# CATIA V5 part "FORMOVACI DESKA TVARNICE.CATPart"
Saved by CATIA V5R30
Part number: FORMOVACI DESKA TVARNICE
Bounding box of the stored display mesh (mm): x 0 to 66, y -248 to 248, z -173 to 173
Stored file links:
  C:\Users\ondra\Desktop\PŘÍLOHA P III\CATIA\FORMOVACI DESKA TVARNICE.CATPart
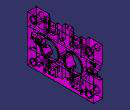
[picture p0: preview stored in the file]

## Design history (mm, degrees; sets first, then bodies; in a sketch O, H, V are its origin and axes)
Set1
  DatumSurface1 to DatumSurface42 "K20/346x"
  Plane1: type Tangent, Support DatumSurface41, RefPoint vertex [face of DatumSurface42]
  Plane2: type Tangent, Support DatumSurface39, RefPoint vertex [face of DatumSurface38]
  Plane3: type Offset, RefPlane yz-plane, Offset 66
  Join1: Elements (DatumSurface1; DatumSurface2; DatumSurface3; DatumSurface4; DatumSurface5; DatumSurface6; DatumSurface7; DatumSurface8; DatumSurface9; DatumSurface10; DatumSurface11; DatumSurface12; DatumSurface13; DatumSurface14; DatumSurface15; DatumSurface16; DatumSurface17; DatumSurface18; DatumSurface19; DatumSurface20; DatumSurface21; DatumSurface22; DatumSurface23; DatumSurface24; DatumSurface25; DatumSurface26; DatumSurface27; DatumSurface28; DatumSurface29; DatumSurface30; DatumSurface31; DatumSurface32; DatumSurface33; DatumSurface34; DatumSurface35; DatumSurface36; DatumSurface37; DatumSurface38; DatumSurface39; DatumSurface40; DatumSurface41; DatumSurface42)
Body1 (main body)
  CloseSurface1: CloseElement Join1
  DatumCurve1 to DatumCurve4
  Sketch1 on yz-plane, origin (0, 0, 0), H (0, 1, 0), V (0, 0, 1)
    projected arc E1 centre (0, 0) radius 9 from (0, 9) to (0, -9) ccw from edge of DatumCurve3
    projected arc E2 centre (0, 0) radius 9 from (0, -9) to (0, 9) ccw from edge of DatumCurve4
  Pocket1: profile Sketch1, direction (-1, 0, 0), through (limit type 6)
  DatumSurface43
  DatumSurface44
  Sketch2 on yz-plane, origin (0, 0, 0), H (0, 1, 0), V (0, 0, 1)
    reference projected circle E1 centre (-88.524, 0) radius 75 from face of DatumSurface43
    reference projected circle E2 centre (88.524, 0) radius 75 from face of DatumSurface44
    point P1 (-88.524, 0)
    point P2 (88.524, 0)
    concentricity: P1 E1, P2 E2
  Sketch3 on {plane type Tangent, Support face of DatumSurface42, RefPoint Sketch2.P1}, origin (0, -88.524, 0), H (0, 1, 0), V (0, 0, 1)
    point P1 (0, 0)
    reference projected point E1 (0, 0) from Sketch2.P1
    coincidence: E1 P1
  Hole1: placed by Sketch3, at (66, -88.524, 0) direction (-1, 0, 0), diameter 130, through (limit type 6), counterbore diameter 140, counterbore depth 10
  UserPattern1: of Hole1, copies 2, at the points of Sketch2
  Plane4: stored without definition
  Fillet1: radius 1, on edge [face of Hole1 | face of Hole1] (x2); edge [face of UserPattern1 | face of UserPattern1] (x2)
  Sketch4 on zx-plane, origin (0, 0, 0), H (-1, 0, 0), V (0, 0, 1)
    arc A1 centre (0, 0) radius 2.5 from (0, 2.5) to (0, -2.5) ccw
    line L1 (0, -2.5) -> (0, 2.5)
    point P1 (0, -2.5)
    radius A1 = 2.5
    coincidence: P1 V
    vertical: L1 V
  Pocket2: profile Sketch4, direction (0, 1, 0), through (limit type 6), opposite side through (limit type 6)
  Sketch5, origin (66, 0, 0), H (0, 1, 0), V (0, 0, -1), geometry linked from another document
  Pocket3: profile Sketch5, direction (-1, 0, 0), length 7
  Plane5: stored without definition
  Plane6: stored without definition
  Mirror1: of Pocket3, about Plane5
  DatumCurve5
  DatumCurve6
  Sketch6 on Plane6, origin (0, -248, 0), H (-1, 0, 0), V (0, 0, 1)
    point P1 (-47, 71)
    point P2 (-47, -71)
    point P3 (13, 71)
    construction line L1 (-47, -71) -> (-47, 71)
    reference projected line E1 (-66, 173) -> (-66, -173) from edge of DatumCurve6
    reference projected line E2 (-66, 173) -> (0, 173) from edge [face of CloseSurface1 | face of CloseSurface1]
    reference projected line E3 (0, -173) -> (-66, -173) from edge [face of CloseSurface1 | face of CloseSurface1]
    distance P1 E1 = 19
    distance P1 E2 = 102
    distance P2 E3 = 102
    vertical: L1 V
  Sketch7 on {plane type Tangent, Support face of CloseSurface1, RefPoint Sketch6.P1}, origin (47, -248, 71), H (1, 0, 0), V (0, 0, -1)
    point P1 (0, 0)
    reference projected point E1 (0, 0) from Sketch6.P1
    coincidence: E1 P1
  Hole2: placed by Sketch7, at (47, -248, 71) direction (0, 1, 0), diameter 8.376, through (limit type 6), counterbore diameter 14, counterbore depth 3, threaded "M10", thread diameter 10, thread depth 9, pitch 1.5
  Plane7: stored without definition
  UserPattern2: of Hole2, copies 2, at the points of Sketch6
  Sketch8 on Plane7, origin (0, 0, -173), H (1, 0, 0), V (0, -1, 0)
    point P1 (47, 137.5)
    point P2 (47, -137.5)
    construction line L1 (47, -137.5) -> (47, 137.5)
    reference projected line E1 (66, -248) -> (66, 248) from edge [face of CloseSurface1 | face of CloseSurface1]
    distance E1 L1 = 19
    length L1 = 275
    symmetry: P1 P2 H
    vertical: L1 V
  Sketch9 on {plane type Tangent, Support face of CloseSurface1, RefPoint Sketch8.P1}, origin (48, -137.5, -173), H (1, 0, 0), V (0, 1, 0)
    point P1 (-1, 0)
    reference projected point E1 (-1, 0) from Sketch8.P1
    coincidence: E1 P1
  Hole3: placed by Sketch9, at (47, -137.5, -173) direction (0, 0, 1), diameter 8.376, depth 110, V-bottom angle 120, counterbore diameter 16, counterbore depth 17, threaded "M10", thread diameter 10, thread depth 8, pitch 1.5
  UserPattern3: of Hole3, copies 2, at the points of Sketch8
  Plane8: stored without definition
  Mirror2: of UserPattern3, about Plane8
  Plane9: stored without definition
  Plane10: type Offset, RefPlane Plane9, Offset 248, reversed
  Plane11: type Offset, RefPlane Plane10, Offset 496
  Plane12: type Offset, RefPlane xy-plane, Offset 173
  Plane13: type Offset, RefPlane xy-plane, Offset 173, reversed
  DatumCurve7 to DatumCurve9
  Sketch10 on Plane11, origin (0, 248, 0), H (-1, 0, 0), V (0, 0, 1)
    reference projected line E3 (-8.3275, -47.5) -> (3.6725, -47.5) from edge of DatumCurve8
    line L1 (0, 47.5) -> (-19.3275, 47.5)
    line L2 (-19.3275, 47.5) -> (-19.3275, -47.5)
    line L3 (-19.3275, -47.5) -> (0, -47.5)
    line L4 (0, -47.5) -> (0, 47.5)
    point P8 (-19.3275, -47.5)
    reference projected line E4 (-19.3275, -47) -> (-19.3275, -32) from edge of DatumCurve9
    horizontal: L1 H, L3 H
    vertical: L2 V, L4 V
    coincidence: P8 E3, E4 L2
  Pocket4: profile Sketch10, direction (0, -1, 0), length 71
  DatumSurface45
  Sketch11 on Plane11, origin (0, 248, 0), H (-1, 0, 0), V (0, 0, 1)
  Pocket5: profile Sketch11, direction (0, -1, 0), length 65
  DatumCurve10 to DatumCurve16
  Sketch12 on Plane11, origin (0, 248, 0), H (-1, 0, 0), V (0, 0, 1)
    projected line E1 (-36.4678, -19) -> (-36.4678, 19) from edge [face of Pocket5 | face of CloseSurface1]
    projected line E2 (-46.4678, 19) -> (-36.4678, 19) from edge of DatumCurve10
    projected line E3 (-46.4678, 19) -> (-46.4678, 18.8) from edge of DatumCurve11
    projected line E4 (-46.4678, 12.8) -> (-46.4678, 18.8) from edge of DatumCurve12
    projected line E5 (-46.4678, 12.8) -> (-46.4678, -12.8) from edge of DatumCurve13
    projected line E6 (-46.4678, -18.8) -> (-46.4678, -12.8) from edge of DatumCurve14
    projected line E7 (-46.4678, -18.8) -> (-46.4678, -19) from edge of DatumCurve15
    projected line E8 (-46.4678, -19) -> (-36.4678, -19) from edge of DatumCurve16
  Pocket6: profile Sketch12, direction (0, -1, 0), length 65, opposite side length -40
  Fillet2: radius 6, on edge [start face of Pocket6 | face of Pocket6] (x2); edge [face of Pocket6 | face of Pocket6] (x2)
  DatumCurve17 to DatumCurve19
  Sketch13 on yz-plane, origin (0, 0, 0), H (0, 1, 0), V (0, 0, 1)
    reference projected line E3 (220.3458, -34.5) -> (170.3458, -34.5) from edge of DatumCurve19
    reference projected line E4 (177, 47.5) -> (177, -47.5) from edge [end face of Pocket4 | face of CloseSurface1]
    line L1 (177, -34.5) -> (170.3458, -34.5)
    point P9 (177, -34.5)
    line L2 (170.3458, -34.5) -> (170.3458, 34.5)
    line L3 (170.3458, 34.5) -> (177, 34.5)
    point P10 (177, 34.5)
    line L4 (177, 34.5) -> (177, -34.5)
    coincidence: P9 E4, P9 E3, P10 E4
    horizontal: L1 H, L3 H
    vertical: L2 V, L4 V
  Pocket7: profile Sketch13, direction (1, 0, 0), length 10
  Plane14: type Offset, RefPlane xy-plane, Offset 31.5, reversed
  DatumCurve20 to DatumCurve23
  Sketch14 on Plane14, origin (0, 0, -31.5), H (1, 0, 0), V (0, 1, 0)
    projected arc E2 centre (22.3275, 212.394) radius 2 from (24.3275, 212.394) to (23.0115, 214.2733) ccw from edge of DatumCurve21
    line L1 (10.1275, 218.9627) -> (0, 218.9627)
    point P7 (0, 218.9627)
    reference projected line E4 (4.3275, 147.5358) -> (24.3275, 147.5358) from edge of DatumCurve23
    line L2 (0, 218.9627) -> (0, 147.5358)
    point P10 (0, 147.5358)
    line L3 (0, 147.5358) -> (24.3275, 147.5358)
    line L4 (24.3275, 147.5358) -> (24.3275, 212.394)
    line L5 (23.0115, 214.2733) -> (10.1275, 218.9627)
    coincidence: P7 V, P10 E4
    horizontal: L1 H, L3 H
    vertical: L2 V
    tangency: L4 E2, L5 E2
  Pocket8: profile Sketch14, direction (0, 0, 1), length 63
  Sketch15 on face of Pocket8 from Sketch14.L3, origin (0, 147.5358, 0), H (-1, 0, 0), V (0, 0, 1)
    line L1 (-24.3275, -31.5) -> (0, -31.5)
    line L2 (0, -31.5) -> (0, 31.5)
    line L3 (0, 31.5) -> (-24.3275, 31.5)
    line L4 (-24.3275, 31.5) -> (-24.3275, -31.5)
    horizontal: L1 H, L3 H
    vertical: L2 V, L4 V
  Pocket9: profile Sketch15, direction (0, -1, 0), length 5
  Mirror3: of Pocket4, Pocket5, Pocket6, Fillet2, Pocket7, Pocket8, Pocket9, about zx-plane
  DatumCurve24 to DatumCurve27
  Sketch16 on Plane12, origin (0, 0, 173), H (1, 0, 0), V (0, 1, 0)
    point P11 (0, 148.524)
    line L1 (0, 148.524) -> (26.5427, 148.524)
    line L2 (26.5427, 148.524) -> (26.5427, 28.524)
    line L3 (26.5427, 28.524) -> (0, 28.524)
    line L4 (0, 28.524) -> (0, 148.524)
    point P13 (26.5427, 28.524)
    point P16 (0, -148.524)
    line L5 (0, -148.524) -> (26.5427, -148.524)
    point P17 (26.5427, -28.524)
    line L6 (26.5427, -148.524) -> (26.5427, -28.524)
    line L7 (26.5427, -28.524) -> (0, -28.524)
    line L8 (0, -28.524) -> (0, -148.524)
    coincidence: P11 V
    horizontal: L1 H, L3 H
    vertical: L2 V, L4 V
    symmetry: P11 P16 H, P13 P17 H
  Pocket10: profile Sketch16, direction (0, 0, -1), length 101.008
  DatumCurve28 to DatumCurve30
  Sketch17 on face of Pocket10 from Sketch16.L6, origin (26.5427, 0, 0), H (0, -1, 0), V (0, 0, 1)
    reference projected line E1 (62.024, 171.9919) -> (62.024, 147.7272) from edge of DatumCurve28
    reference projected line E2 (148.524, 173) -> (28.524, 173) from edge [face of CloseSurface1 | face of Pocket10 from Sketch16.L6]
    reference projected line E3 (108.824, 100.9919) -> (68.224, 100.9919) from edge of DatumCurve29
    reference projected line E4 (115.024, 147.7272) -> (115.024, 171.9919) from edge of DatumCurve30
    point P9 (62.024, 173)
    line L1 (62.024, 173) -> (115.024, 173)
    line L2 (115.024, 173) -> (115.024, 100.9919)
    line L3 (115.024, 100.9919) -> (62.024, 100.9919)
    line L4 (62.024, 100.9919) -> (62.024, 173)
    point P10 (115.024, 173)
    point P11 (115.024, 100.9919)
    point P12 (62.024, 100.9919)
    point P13 (-115.024, 173)
    point P14 (-62.024, 173)
    line L5 (-62.024, 173) -> (-115.024, 173)
    point P15 (-115.024, 100.9919)
    line L6 (-115.024, 173) -> (-115.024, 100.9919)
    point P16 (-62.024, 100.9919)
    line L7 (-115.024, 100.9919) -> (-62.024, 100.9919)
    line L8 (-62.024, 100.9919) -> (-62.024, 173)
    coincidence: P9 E2, P9 E1, P11 E4, P11 E3
    horizontal: L1 H, L3 H
    vertical: L2 V, L4 V
    symmetry: P10 P13 V, P9 P14 V, L1 L5 V, P11 P15 V, L2 L6 V, P12 P16 V, L3 L7 V, L4 L8 V
  Pocket11: profile Sketch17, direction (1, 0, 0), length 15
  DatumCurve31 to DatumCurve34
  Sketch18 on face of Pocket10 from Sketch16.L6, origin (26.5427, 0, 0), H (0, -1, 0), V (0, 0, 1)
    reference projected line E1 (108.824, 100.9919) -> (68.224, 100.9919) from edge of DatumCurve31
    reference projected line E2 (115.024, 119.7919) -> (115.024, 107.1919) from edge of DatumCurve32
    reference projected line E3 (68.224, 125.9919) -> (108.824, 125.9919) from edge of DatumCurve33
    reference projected line E4 (62.024, 107.1919) -> (62.024, 119.7919) from edge of DatumCurve34
    point P9 (62.024, 125.9919)
    line L1 (62.024, 125.9919) -> (115.024, 125.9919)
    line L2 (115.024, 125.9919) -> (115.024, 100.9919)
    line L3 (115.024, 100.9919) -> (62.024, 100.9919)
    line L4 (62.024, 100.9919) -> (62.024, 125.9919)
    point P10 (115.024, 125.9919)
    point P11 (115.024, 100.9919)
    point P12 (62.024, 100.9919)
    point P13 (-115.024, 100.9919)
    point P14 (-115.024, 125.9919)
    line L5 (-115.024, 125.9919) -> (-115.024, 100.9919)
    point P15 (-62.024, 125.9919)
    line L6 (-62.024, 125.9919) -> (-115.024, 125.9919)
    point P16 (-62.024, 100.9919)
    line L7 (-62.024, 100.9919) -> (-62.024, 125.9919)
    line L8 (-115.024, 100.9919) -> (-62.024, 100.9919)
    coincidence: P9 E4, P9 E3, P11 E2, P11 E1
    horizontal: L1 H, L3 H
    vertical: L2 V, L4 V
    symmetry: P11 P13 V, P10 P14 V, L2 L5 V, P9 P15 V, L1 L6 V, P12 P16 V, L4 L7 V, L3 L8 V
  Pocket12: profile Sketch18, direction (1, 0, 0), length 27
  Fillet3: radius 6, on edge [face of Pocket12 | face of Pocket12] (x4); edge [face of Pocket12 from Sketch18.L1 | face of Pocket12]; edge [face of Pocket12 | face of Pocket12 from Sketch18.L1]; edge [face of Pocket12 from Sketch18.L6 | face of Pocket12]; edge [face of Pocket12 | face of Pocket12 from Sketch18.L6]
  DatumCurve35 to DatumCurve39
  Sketch19 on yz-plane, origin (0, 0, 0), H (0, 1, 0), V (0, 0, 1)
    reference projected line E1 (-54.0014, 37.4203) -> (-54.0014, 57.0375) from edge of DatumCurve35
    point P2 (-54.0014, 57.0375)
    point P3 (-48.524, 57.0375)
    reference projected line E3 (-123.0467, 37.4203) -> (-123.0467, 57.0375) from edge of DatumCurve37
    point P6 (-123.0467, 57.0375)
    reference projected line E4 (-128.524, 87.0375) -> (-128.524, 57.0375) from edge of DatumCurve38
    point P8 (-128.524, 57.0375)
    reference projected line E5 (-48.524, 57.0375) -> (-48.524, 87.0375) from edge of DatumCurve39
    reference projected arc E6 centre (-88.524, 0) radius 65 from (-23.5721, 2.5) to (-145.3813, 31.5) ccw from edge [face of CloseSurface1 | face of Hole1]
    line L1 (-54.0014, 55.0743) -> (-123.0467, 55.0743)
    point P13 (-54.0014, 55.0743)
    point P14 (-123.0467, 55.0743)
    line L2 (-54.0014, 55.0743) -> (-54.0014, 57.0375)
    line L3 (-54.0014, 57.0375) -> (-48.524, 57.0375)
    line L4 (-48.524, 57.0375) -> (-48.524, 72.0375)
    point P15 (-48.524, 72.0375)
    line L5 (-48.524, 72.0375) -> (-128.524, 72.0375)
    point P16 (-128.524, 72.0375)
    line L6 (-128.524, 72.0375) -> (-128.524, 57.0375)
    line L7 (-128.524, 57.0375) -> (-123.0467, 57.0375)
    line L8 (-123.0467, 57.0375) -> (-123.0467, 55.0743)
    point P17 (123.0467, 55.0743)
    point P18 (54.0014, 55.0743)
    line L9 (54.0014, 55.0743) -> (123.0467, 55.0743)
    point P19 (123.0467, 57.0375)
    line L10 (123.0467, 57.0375) -> (123.0467, 55.0743)
    point P20 (128.524, 57.0375)
    line L11 (128.524, 57.0375) -> (123.0467, 57.0375)
    point P21 (128.524, 72.0375)
    line L12 (128.524, 72.0375) -> (128.524, 57.0375)
    point P22 (48.524, 72.0375)
    line L13 (48.524, 72.0375) -> (128.524, 72.0375)
    point P23 (48.524, 57.0375)
    line L14 (48.524, 57.0375) -> (48.524, 72.0375)
    point P24 (54.0014, 57.0375)
    line L15 (54.0014, 57.0375) -> (48.524, 57.0375)
    line L16 (54.0014, 55.0743) -> (54.0014, 57.0375)
    coincidence: P13 E6, P13 E1, P14 E6, P14 E3
    vertical: L2 V, L4 V, L6 V, L8 V
    horizontal: L3 H, L5 H, L7 H
    midpoint: P15 E5, P16 E4
    symmetry: P14 P17 V, P13 P18 V, L1 L9 V, P6 P19 V, L8 L10 V, P8 P20 V, L7 L11 V, P16 P21 V, L6 L12 V, P15 P22 V, L5 L13 V, P3 P23 V, L4 L14 V, P2 P24 V, L3 L15 V, L2 L16 V
  Pocket13: profile Sketch19, direction (1, 0, 0), length 38
  DatumCurve40 to DatumCurve42
  Sketch20 on yz-plane, origin (0, 0, 0), H (0, 1, 0), V (0, 0, 1)
    point P3 (-48.524, 109.0375)
    point P7 (-128.524, 71.992)
    line L1 (-48.524, 109.0375) -> (-128.524, 109.0375)
    line L2 (-128.524, 109.0375) -> (-128.524, 71.992)
    line L3 (-128.524, 71.992) -> (-48.524, 71.992)
    line L4 (-48.524, 71.992) -> (-48.524, 109.0375)
    point P9 (-128.524, 109.0375)
    point P10 (-48.524, 71.992)
    point P11 (128.524, 109.0375)
    point P12 (48.524, 109.0375)
    line L5 (48.524, 109.0375) -> (128.524, 109.0375)
    point P13 (128.524, 71.992)
    line L6 (128.524, 109.0375) -> (128.524, 71.992)
    point P14 (48.524, 71.992)
    line L7 (128.524, 71.992) -> (48.524, 71.992)
    line L8 (48.524, 71.992) -> (48.524, 109.0375)
    horizontal: L1 H, L3 H
    vertical: L2 V, L4 V
    symmetry: P9 P11 V, P3 P12 V, L1 L5 V, P7 P13 V, L2 L6 V, P10 P14 V, L3 L7 V, L4 L8 V
  Pocket14: profile Sketch20, direction (1, 0, 0), length 38
  Plane15: stored without definition
  Sketch21 on yz-plane, origin (0, 0, 0), H (0, 1, 0), V (0, 0, 1)
    reference projected arc E2 centre (88.5237, -0.0003) radius 65.0004 from (145.3813, 31.5) to (123.0467, 55.0744) ccw from edge [face of CloseSurface1 | face of UserPattern1]
    point P5 (48.524, 57.0375)
    line L1 (48.524, 57.0375) -> (128.524, 57.0375)
    line L2 (128.524, 57.0375) -> (128.524, 51.2347)
    line L3 (128.524, 51.2347) -> (48.524, 51.2347)
    line L4 (48.524, 51.2347) -> (48.524, 57.0375)
    point P9 (128.524, 57.0375)
    point P10 (128.524, 51.2347)
    point P11 (48.524, 51.2347)
    point P12 (-128.524, 57.0375)
    point P13 (-48.524, 57.0375)
    line L5 (-48.524, 57.0375) -> (-128.524, 57.0375)
    point P14 (-128.524, 51.2347)
    line L6 (-128.524, 57.0375) -> (-128.524, 51.2347)
    point P15 (-48.524, 51.2347)
    line L7 (-128.524, 51.2347) -> (-48.524, 51.2347)
    line L8 (-48.524, 51.2347) -> (-48.524, 57.0375)
    horizontal: L1 H, L3 H
    vertical: L2 V, L4 V
    coincidence: P10 E2
    symmetry: P9 P12 V, P5 P13 V, L1 L5 V, P10 P14 V, L2 L6 V, P11 P15 V, L3 L7 V, L4 L8 V
  Pocket15: profile Sketch21, direction (1, 0, 0), length 38
  DatumCurve43 to DatumCurve46
  Sketch22 on Plane15, origin (0, -88.524, 0), H (1, 0, 0), V (0, 0, 1)
    projected arc E1 centre (25.5427, 132.2658) radius 2 from (27.5427, 132.2658) to (26.2267, 134.1452) ccw from edge of DatumCurve43
    line L1 (27.5427, 132.2658) -> (27.5427, 108.7647)
    line L2 (26.2267, 134.1452) -> (26.2267, 108.7647)
    line L3 (26.2267, 108.7647) -> (27.5427, 108.7647)
    vertical: L1 V, L2 V
    horizontal: L3 H
  Pocket16: profile Sketch22, direction (0, 1, 0), length 40, opposite side length 40
  Plane16: stored without definition
  Mirror4: of Pocket10, Pocket11, Pocket12, Fillet3, Pocket13, Pocket14, Pocket15, Pocket16, about xy-plane
  DatumCurve47
  Sketch23 on Plane16, origin (0, 88.524, 0), H (-1, 0, 0), V (0, 0, 1)
    projected arc E1 centre (-25.5427, 132.2658) radius 2 from (-26.2267, 134.1452) to (-27.5427, 132.2658) ccw from edge of DatumCurve47
    line L1 (-26.2267, 134.1452) -> (-26.2267, 108.4376)
    line L2 (-26.2267, 108.4376) -> (-27.5427, 108.4376)
    line L3 (-27.5427, 108.4376) -> (-27.5427, 132.2658)
    vertical: L1 V, L3 V
    horizontal: L2 H
  Pocket17: profile Sketch23, direction (0, -1, 0), length 40, opposite side length 40
  Mirror5: of Pocket17, about xy-plane
  DatumSurface46
  DatumSurface47
  Sketch24 on face of Pocket5, origin (36.4678, 0, 0), H (0, -1, 0), V (0, 0, 1)
    reference projected circle E1 centre (-237, 0) radius 7 from face of DatumSurface46
    reference projected circle E3 centre (237, 0) radius 7 from face of DatumSurface47
    point P1 (237, 0)
    point P2 (-237, 0)
    concentricity: P1 E3, P2 E1
  Sketch25 on face of Pocket5, origin (36.4678, 237, 0), H (0, 1, 0), V (0, 0, -1)
    point P1 (0, 0)
    reference projected point E1 (0, 0) from Sketch24.P2
    coincidence: E1 P1
  Hole4: placed by Sketch25, at (36.4678, 237, 0) direction (1, 0, 0), diameter 8.376, depth 15, V-bottom angle 120, threaded "M10", thread diameter 10, thread depth 13, pitch 1.5
  UserPattern4: of Hole4, copies 2, at the points of Sketch24
  DatumSurface48 to DatumSurface55
  Sketch26 on face of Mirror4, origin (41.5427, 0, 0), H (0, -1, 0), V (0, 0, 1)
    reference projected circle E1 centre (-101.024, 158.9919) radius 7 from face of DatumSurface48
    reference projected circle E3 centre (-76.024, 158.9919) radius 7 from face of DatumSurface49
    reference projected circle E5 centre (76.024, 158.9919) radius 7 from face of DatumSurface50
    reference projected circle E7 centre (101.024, 158.9919) radius 7 from face of DatumSurface51
    reference projected circle E9 centre (-101.024, -158.9919) radius 7 from face of DatumSurface52
    reference projected circle E11 centre (-76.024, -158.9919) radius 7 from face of DatumSurface53
    reference projected circle E13 centre (76.024, -158.9919) radius 7 from face of DatumSurface54
    reference projected circle E15 centre (101.024, -158.9919) radius 7 from face of DatumSurface55
    point P1 (-101.024, -158.9919)
    point P2 (-76.024, -158.9919)
    point P3 (76.024, -158.9919)
    point P4 (101.024, -158.9919)
    point P5 (-101.024, 158.9919)
    point P6 (-76.024, 158.9919)
    point P7 (76.024, 158.9919)
    point P8 (101.024, 158.9919)
    concentricity: P1 E9, P2 E11, P3 E13, P4 E15, P5 E1, P6 E3, P7 E5, P8 E7
  Sketch27 on face of Mirror4, origin (41.5427, 101.024, -158.9919), H (0, 1, 0), V (0, 0, -1)
    point P1 (0, 0)
    reference projected point E1 (0, 0) from Sketch26.P1
    coincidence: E1 P1
  Hole5: placed by Sketch27, at (41.5427, 101.024, -158.9919) direction (1, 0, 0), diameter 8.376, depth 13, V-bottom angle 120, threaded "M10", thread diameter 10, thread depth 11, pitch 1.5
  UserPattern5: of Hole5, copies 8, at the points of Sketch26
  DatumCurve48
  DatumCurve49
  Sketch28 on zx-plane, origin (0, 0, 0), H (-1, 0, 0), V (0, 0, 1)
    reference projected arc E1 centre (-20, 80) radius 12.1003 from (-32.1003, 80) to (-24.947, 68.9571) ccw from edge of DatumCurve48
    reference projected arc E2 centre (-20, -80) radius 12.1003 from (-32.1003, -80) to (-24.947, -91.0429) ccw from edge of DatumCurve49
    point P5 (-20, -80)
    point P6 (-20, 80)
    concentricity: P5 E2, P6 E1
  Sketch29 on {plane type Tangent, Support face of CloseSurface1, RefPoint Sketch28.P6}, origin (20, 0, 80), H (1, 0, 0), V (0, 0, -1)
    point P1 (0, 0)
    reference projected point E1 (0, 0) from Sketch28.P6
    coincidence: E1 P1
  Hole6: placed by Sketch29, at (20, -248, 80) direction (0, 1, 0), diameter 8.376, depth 19, V-bottom angle 120, threaded "M10", thread diameter 10, thread depth 17, pitch 1.5
  UserPattern6: of Hole6, copies 2, at the points of Sketch28
  DatumSurface56
  Sketch30 on xy-plane, origin (0, 0, 0), H (1, 0, 0), V (0, 1, 0)
    reference projected circle E1 centre (12, 0) radius 7 from face of DatumSurface56
    point P1 (12, 0)
    concentricity: P1 E1
  Sketch31 on {plane type Tangent, Support face of CloseSurface1, RefPoint Sketch30.P1}, origin (12, 0, 0), H (1, 0, 0), V (0, 1, 0)
    point P1 (0, 0)
    reference projected point E1 (0, 0) from Sketch30.P1
    coincidence: E1 P1
  Hole7: placed by Sketch31, at (12, 0, -173) direction (0, 0, 1), diameter 6.647, depth 13, V-bottom angle 120, threaded "M8", thread diameter 8, thread depth 11, pitch 1.25
  Mirror6: of Hole7, about xy-plane
  Sketch32 on {plane type Tangent, Support face of CloseSurface1, RefPoint Sketch6.P1}, origin (47, -248, 71), H (1, 0, 0), V (0, 0, 1)
    point P1 (0, 0)
    reference projected point E1 (0, 0) from Sketch6.P1
    coincidence: E1 P1
  Hole8: placed by Sketch32, at (47, 248, 71) direction (0, -1, 0), diameter 8.376, depth 12, counterbore diameter 14, counterbore depth 3, threaded "M10", thread diameter 10, thread depth 9, pitch 1.5
  UserPattern7: of Hole8, copies 2, at the points of Sketch6
  Plane17: type Offset, RefPlane Plane10, Offset 3
  Plane18: type Offset, RefPlane Plane11, Offset 3, reversed
  Plane19: type Offset, RefPlane Plane13, Offset 17
  Plane20: type Offset, RefPlane Plane12, Offset 17, reversed
Body2
  Plane21: type Offset, RefPlane Plane17, Offset 6
  Plane22: type Offset, RefPlane Plane18, Offset 6, reversed
  Plane23: type Offset, RefPlane Plane19, Offset 7
  Plane24: type Offset, RefPlane Plane20, Offset 7, reversed
  Sketch33 on Plane21, origin (0, -239, 0), H (-1, 0, 0), V (0, 0, 1)
    projected circle E1 centre (-47, 71) radius 4.188 from edge [face of Hole2 | face of Hole8]
    projected circle E2 centre (-47, -71) radius 4.188 from edge [face of UserPattern2 | face of UserPattern7]
  Pad1: profile Sketch33, direction (0, 1, 0), up to Plane22
  Sketch34 on Plane24, origin (0, 0, 149), H (1, 0, 0), V (0, 1, 0)
    projected circle E1 centre (47, -137.5) radius 4.188 from edge [face of Mirror2 | face of Mirror2]
    projected circle E2 centre (47, 137.5) radius 4.188 from edge [face of Mirror2 | face of Mirror2]
  Pad2: profile Sketch34, direction (0, 0, -1), length 90
  Mirror7: of Pad2, about xy-plane
  Body3
    Solid1: linked copy from another document
  Remove1: tool Body3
